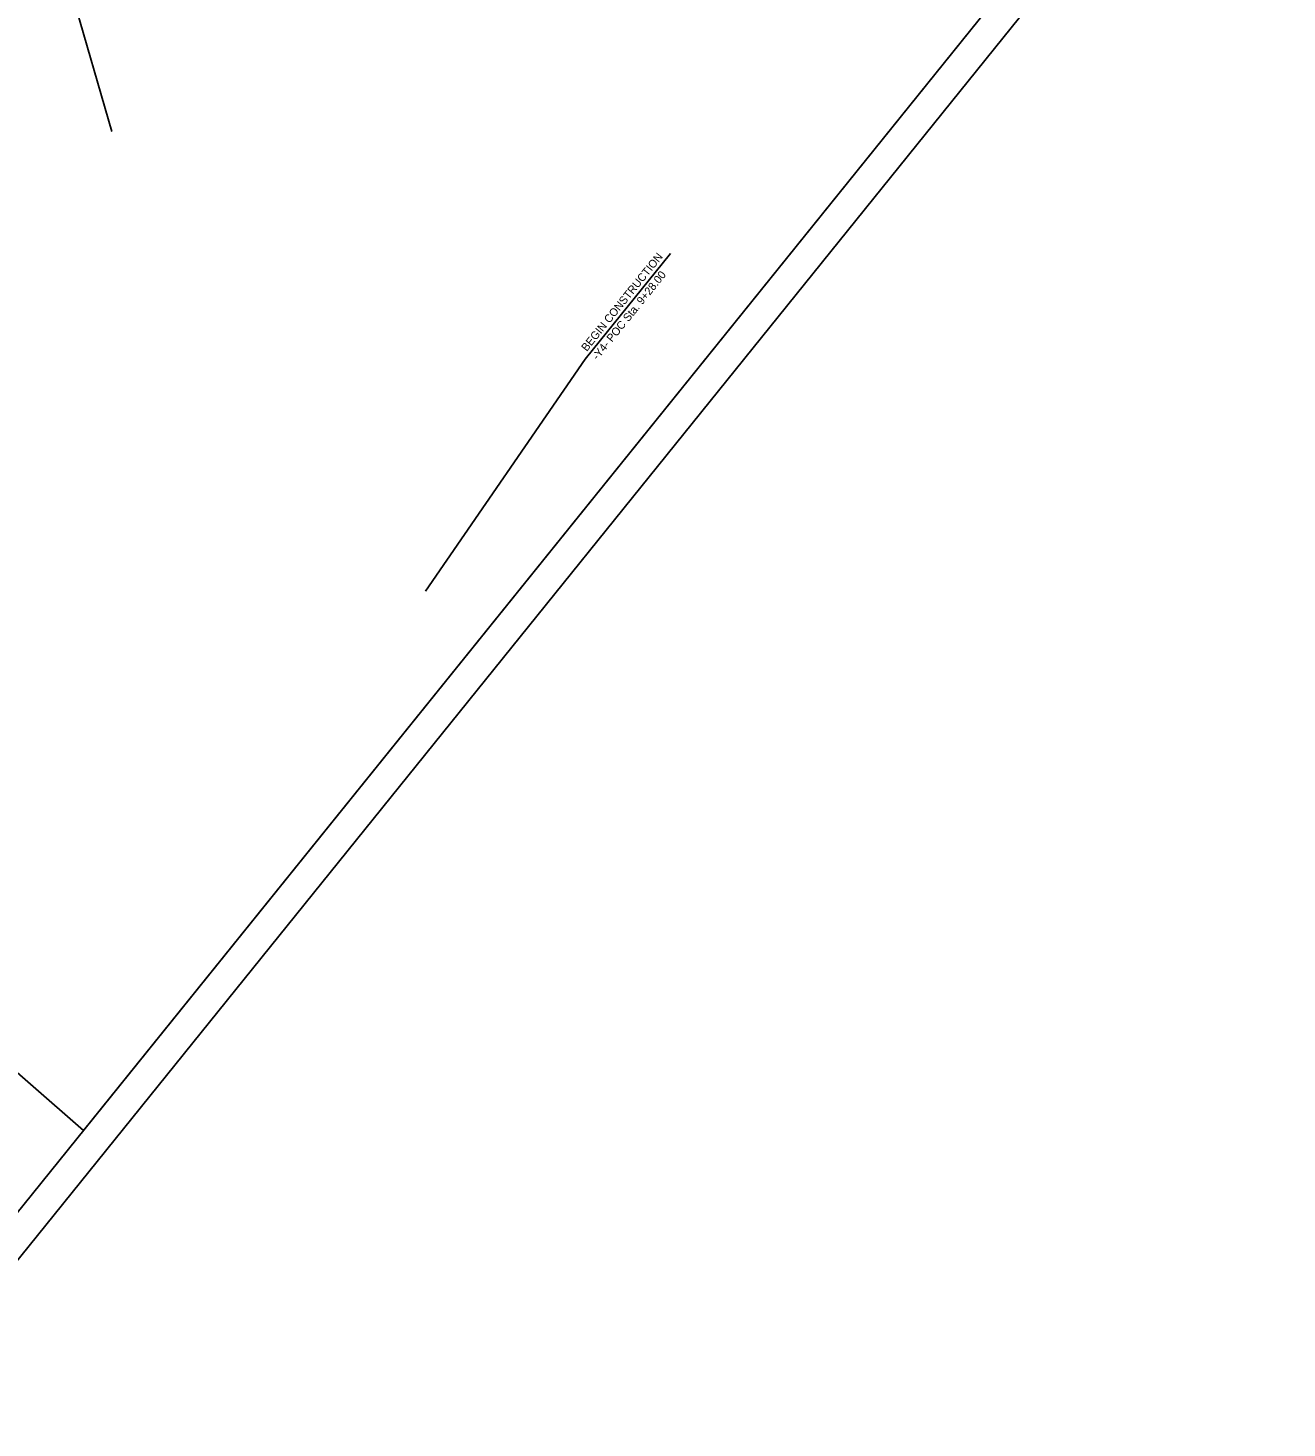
# Model space of a CAD drawing. Extents: x 1487875 to 1489967, y 498345 to 500495.
# Drawn here: x 1488837 to 1489784, y 498345 to 499398 of the extents above; entities that cross this region are included whole.
import ezdxf

# ---------------------------------------------------------------- set-up
doc = ezdxf.new("R2010")
doc.units = 0
for name, color, linetype in [('Exist Utilities Sanitary Sewer Manhole CELL', 7, 'Continuous'), ('Exist Utilities TV UG Cable SUE LOS C', 7, 'Continuous'), ('Exist Utilities Water Fire Hydrant CELL', 7, 'Continuous'), ('Prop UG Pow Cables', 7, 'Continuous')]:
    doc.layers.add(name, color=color, linetype=linetype)

msp = doc.modelspace()

# ---------------------------------------------------------------- linework, layer by layer
at = {"layer": 'Exist Utilities Sanitary Sewer Manhole CELL'}
for p, q in [((1488900.6, 499320), (1488846.3, 499507.9)), ((1489256.6, 499149), (1489320.6, 499228.3)), ((1489136.5, 498974.4), (1489256.6, 499149))]:
    msp.add_line(p, q, dxfattribs=at)
at = {"layer": 'Exist Utilities TV UG Cable SUE LOS C'}
for points in [[(1488938.9, 500315.8), (1487997.2, 499148.2), (1488814.5, 498489), (1489756.2, 499656.7)], [(1488814.5, 498489), (1487997.2, 499148.1), (1488813.3, 500160.1), (1488842.5, 500136.5), (1488968.1, 500292.2), (1489756.2, 499656.7)]]:
    msp.add_lwpolyline(points, close=True, dxfattribs=at)
at = {"layer": 'Exist Utilities Water Fire Hydrant CELL'}
msp.add_lwpolyline([(1488842.5, 500136.5), (1488813.3, 500160.1), (1488087.8, 499260.5), (1488879.1, 498569.1), (1489756.2, 499656.7), (1488968.1, 500292.2)], close=True, dxfattribs=at)
msp.add_lwpolyline([(1488842.5, 500136.5), (1488813.3, 500160.1), (1488087.8, 499260.5), (1488879.1, 498569.1), (1489756.2, 499656.7), (1488968.1, 500292.2)], close=True, dxfattribs=at)
at = {"layer": 'Prop UG Pow Cables'}
msp.add_lwpolyline([(1488727.6, 498345.3), (1489784.4, 499655.8), (1488932, 500343.2), (1487875.2, 499032.7)], close=True, dxfattribs=at)

# ---------------------------------------------------------------- texts
at = {"layer": 'Exist Utilities Sanitary Sewer Manhole CELL'}
for s, p in [('BEGIN CONSTRUCTION', (1489257.7, 499154.3)), ('-Y4- POC Sta. 9+28.00', (1489265.8, 499147.8))]:
    msp.add_text(s, height=6, rotation=51.1156, dxfattribs=at).set_placement(p)

doc.saveas('drawing.dxf')
